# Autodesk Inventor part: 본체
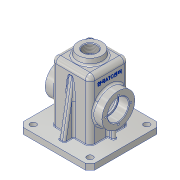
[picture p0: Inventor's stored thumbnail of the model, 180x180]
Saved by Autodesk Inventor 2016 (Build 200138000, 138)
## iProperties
Created: 2018-10
Part Number: 본체
Material: 알루미늄 6061
Document SubType Name: Modeling
Designer: user
Density: 2.7 g/cm^3
Appearance: 알루미늄 - 평지
Mass: 794.227 g
Surface Area: 899.5 cm^2
Volume: 294.158 cm^3
Author: user
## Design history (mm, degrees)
sketch "스케치1"
  geometry: L1 (60, 60)-(-60, 60); L2 (-60, 60)-(-60, -60); L3 (-60, -60)-(60, -60); L4 (60, -60)-(60, 60); L5 (60, 60)-(-60, -60); L6 (-60, 60)-(60, -60); 1 further point
  constraints: 12 end point, 2 midpoint, 2 parallel, 1 horizontal, 1 perpendicular
  dimensions: "d0" = 120 distance of L3.end L2.end; "d1" = 120 distance of L2.end L1.end
extrude "돌출1" new body sketch "스케치1" distance "d2" = 10; taper "d3" = 0 deg
sketch "스케치2"
  geometry: L1 (-32.5, 32.5)-(32.5, 32.5); L2 (32.5, 32.5)-(32.5, -32.5); L3 (32.5, -32.5)-(-32.5, -32.5); L4 (-32.5, -32.5)-(-32.5, 32.5); L5 (-32.5, 32.5)-(32.5, -32.5); L6 (32.5, 32.5)-(-32.5, -32.5); 1 further point
  constraints: 12 end point, 2 midpoint, 2 parallel, 1 horizontal, 1 perpendicular
  dimensions: "d4" = 65 distance of L2.end L3.end; "d5" = 65 distance of L1.end L2.end
extrude "돌출2" join sketch "스케치2" distance "d6" = 100; taper "d7" = 0 deg
feature "쉘1" dims "d8" = 10, "d9" = 5
node "작업 평면1"
sketch "스케치3"
  geometry: C1 r 20 at (0, 0); 1 further point
  constraints: 1 centre point, 1 coincident
  dimensions: "d11" = 40 diameter of C1
extrude "돌출3" join sketch "스케치3" stored distance "d12" = 100; taper "d13" = 7 deg
sketch "스케치4"
  geometry: 2 further points
  constraints: 1 coincident
hole "구멍1" sketch "스케치4" at (0, 0) diameter "d14" = 22.835; stored, may be unused: countersink angle "d18" = 90 deg, drill point angle "d20" = 118 deg; dims "d15" = 50, "d16" = 4, "d17" = 2, "d19" = 59.3
sketch "스케치5"
  geometry: L1 (-27.5, 0)-(92.5, 0) reference; L2 (-27.5, -10)-(92.5, -10) reference; C1 r 27.5 at (32.5, 45); 2 further points
  constraints: 1 centre point, 1 midpoint, 1 vertical alignment
  dimensions: "d21" = 55 diameter of C1; "d22" = 55 distance from line of L2 C1.centre
extrude "돌출4" join sketch "스케치5" distance "d23" = 15; taper "d24" = 0 deg
sketch "스케치6"
  geometry: C1 r 27.5 at (0, 0) reference; C2 r 17.5 at (0, 0); C3 r 15 at (0, 0); 1 further point
  constraints: 2 centre point, 2 coincident
  dimensions: "d25" = 35 diameter of C2; "d26" = 30 diameter of C3
extrude "돌출5" cut sketch "스케치6" distance "d27" = 17; taper "d28" = 0 deg
extrude "돌출6" cut sketch "스케치6" stored distance "d29" = 17; taper "d30" = 0 deg
sketch "스케치7" dims "d31" = 42
  geometry: 5 further points
  constraints: 2 vertical alignment, 1 coincident, 2 other
hole "구멍2" sketch "스케치7" at (0, 21) diameter "d32" = 3.242; stored, may be unused: countersink angle "d36" = 90 deg, drill point angle "d38" = 118 deg; dims "d33" = 8, "d34" = 4, "d35" = 2, "d37" = 10
sketch "스케치8"
  geometry: L1 (92.5, 0)-(92.5, -10) reference; L2 (92.5, -10)-(-27.5, -10) reference; L3 (-27.5, -10)-(-27.5, 0) reference; L4 (-27.5, 0)-(0, 0) reference; L5 (0, 0)-(65, 0) reference; L6 (65, 0)-(92.5, 0) reference; L7 (0, 0)-(0, 100) reference; L8 (0, 100)-(65, 100) reference; L9 (65, 100)-(65, 0) reference; L10 (0, 0)-(65, 0) reference; L11 (29.5, 0)-(35.5, 0); L12 (35.5, 0)-(35.5, 20.13); L13 (35.5, 20.13)-(29.5, 20.13); L14 (29.5, 20.13)-(29.5, 0); C1 r 17.5 at (32.5, 45) reference; C2 r 27.5 at (32.5, 45) reference; 3 further points
  constraints: 8 end point, 2 midpoint, 2 parallel, 1 horizontal, 1 perpendicular, 1 point on line, 1 vertical alignment
  dimensions: "d42" = 6 distance between parallel lines of L14 L12
extrude "돌출7" join sketch "스케치8" distance "d43" = 10; taper "d44" = 0 deg
node "작업 평면2"
sketch "스케치9"
  geometry: L1 (-60, 95)-(-60, -10) reference; L2 (-60, -10)-(-92.5, -10) reference; L3 (-92.5, -10)-(-92.5, 0) reference; L4 (-92.5, 0)-(-65, 0) reference; L5 (-65, 0)-(-65, 100) reference; L6 (-65, 100)-(-53.728, 100) reference; L7 (-53.728, 100)-(-52.5, 110) reference; L8 (-52.5, 110)-(-43.918, 110) reference; L9 (-43.918, 110)-(-43.918, 95) reference; L10 (-43.918, 95)-(-60, 95) reference; L11 (-5, -10)-(-5, 95) reference; L12 (-5, 95)-(-21.082, 95) reference; L13 (-21.082, 95)-(-21.082, 110) reference; L14 (-21.082, 110)-(-12.5, 110) reference; L15 (-12.5, 110)-(-11.272, 100) reference; L16 (-11.272, 100)-(0, 100) reference; L17 (0, 100)-(0, 0) reference; L18 (0, 0)-(27.5, 0) reference; L19 (27.5, 0)-(27.5, -10) reference; L20 (27.5, -10)-(-5, -10) reference; L21 (27.5, 0)-(-92.5, 0) reference; L22 (15.5, 0)-(0, 87.905); L23 (0, 0)-(0, 100) reference; 1 further point
  constraints: 2 end point, 2 point on line
  dimensions: "d45" = 10 deg angle of L19 L22; "d46" = 12 distance from line of L19 L22.start
extrude "돌출8" join sketch "스케치9" stored distance "d47" = 10; taper "d48" = 0 deg
sketch "스케치10"
  geometry: L1 (-65, 0)-(-65, 100) reference; L2 (-52.5, 110)-(-12.5, 110) reference; 2 further points
  constraints: 1 other
  dimensions: "d49" = 32.5 distance from line of L1 point (-32.5, 84); "d50" = 26 distance from line of L2 point (-32.5, 84)
feature "엠보싱1" sketch "스케치10" dims "d51" = 0.5, "d52" = 0
sketch "스케치11"
  geometry: L1 (47.5, 47.5)-(-47.5, 47.5); L2 (-47.5, 47.5)-(-47.5, -47.5); L3 (-47.5, -47.5)-(47.5, -47.5); L4 (47.5, -47.5)-(47.5, 47.5); L5 (47.5, 47.5)-(-47.5, -47.5); L6 (-47.5, 47.5)-(47.5, -47.5); 5 further points
  constraints: 12 end point, 4 coincident, 2 midpoint, 2 parallel, 1 horizontal, 1 perpendicular
  dimensions: "d53" = 95 distance of L3.end L2.end; "d54" = 95 distance of L2.end L1.end
hole "구멍3" sketch "스케치11" at (-47.5, 47.5), (-47.5, -47.5), (47.5, -47.5), (47.5, 47.5) diameter "d55" = 10; stored, may be unused: countersink angle "d59" = 90 deg, drill point angle "d61" = 118 deg; dims "d56" = 8, "d57" = 4, "d58" = 2, "d60" = 10
chamfer "모따기1" distance "d62" = 8; stored, may be unused: second distance "d63" = 2, angle "d64" = 45 deg
chamfer "모따기2" distance "d65" = 1; stored, may be unused: second distance "d66" = 2, angle "d67" = 45 deg
fillet "모깎기1" dims "d68" = 8
fillet "모깎기2" dims "d69" = 8
fillet "모깎기3" dims "d70" = 3
fillet "모깎기4" dims "d71" = 3
fillet "모깎기5" dims "d72" = 3
fillet "모깎기6" dims "d73" = 1
fillet "모깎기7" dims "d74" = 0.3
node "솔리드1"
pattern_circular "원형 패턴1" dims angle "d40" = 360 deg
mirror "대칭1"
mirror "대칭2"
node "절단 모서리 투영1"
node "절단 모서리 투영2"
